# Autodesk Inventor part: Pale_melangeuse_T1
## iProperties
Shininess: 64.0
Length Units: 11269
Angle Units: 11279
Time Units: 11290
Mass Units: 11283
Length Display Precision: 3
Angle Display Precision: 2
Compacted: True
Part Number: Pale_melangeuse_T1
Document SubType Name: Modeling
Created: 2008-02
Material: Acier inoxydable, austénitique
Designer: Pascal
Density: 0.0
Volumn: 0.0
Area: 0.0
PropertySet Name: Model Information
Control State: 0
Master: False
Checked Out: False
DESIGNATION: pièce
Author: Pascal
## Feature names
1. Extrusion1
